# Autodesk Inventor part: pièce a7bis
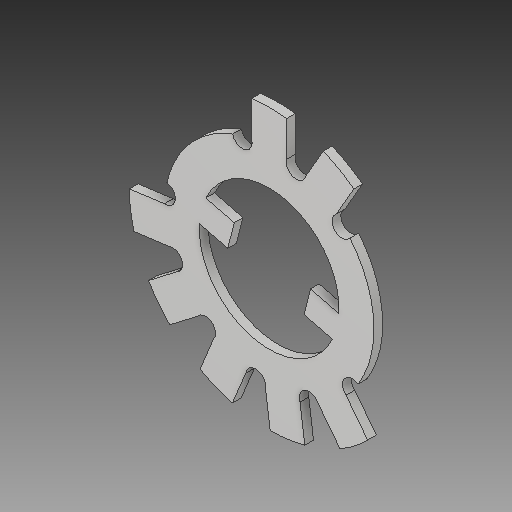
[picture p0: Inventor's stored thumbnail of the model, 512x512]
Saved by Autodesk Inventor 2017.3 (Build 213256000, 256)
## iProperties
Created: 2007-12
Part Number: pièce a7bis
Material: Générique
Document SubType Name: Modeling
Designer: ficho
Density: 1 g/cm^3
Appearance: Par défaut
Author: ficho
Sending System: SolidWorks 2009
Last Author: christophe
Last Saved: 2011-02-10
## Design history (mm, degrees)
extrude "Extrusion1"
node "Solide1"
